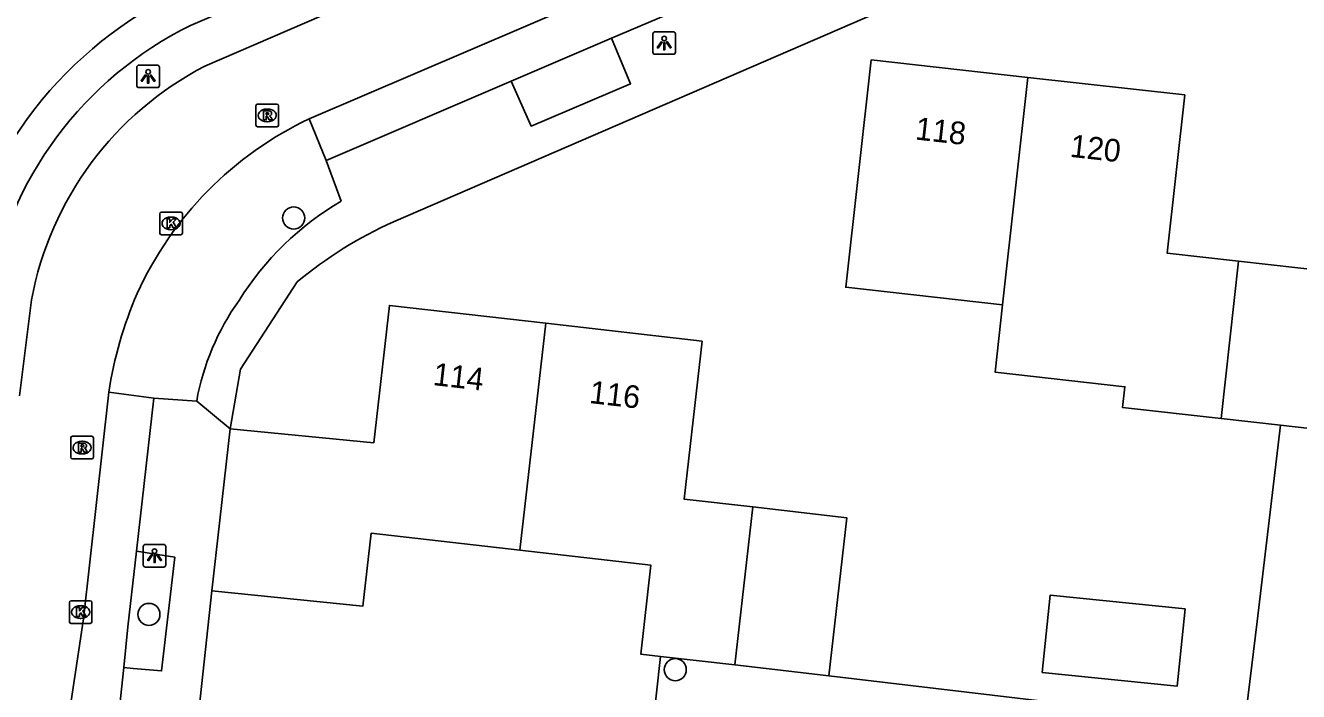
# Model space of a CAD drawing. Extents: x 162026 to 163499, y 387297 to 388169.
# Drawn here: x 162195.3 to 162251.6, y 387941.9 to 387971.3 of the extents above; entities that cross this region are included whole.
import ezdxf

# ---------------------------------------------------------------- set-up
doc = ezdxf.new("R2010")
doc.units = 0
for name, color, linetype in [('IMGEO_Boom', 7, 'Continuous'), ('IMGEO_Kolk', 7, 'Continuous'), ('IMGEO_Lichtpunt', 7, 'Continuous'), ('IMGEO_Pand', 7, 'Continuous'), ('IMGEO_Pand_nummerreeks', 7, 'Continuous'), ('IMGEO_Parkeervlak_open', 7, 'Continuous'), ('IMGEO_Rijbaan_lokaal_open', 7, 'Continuous'), ('IMGEO_Rioolput', 7, 'Continuous'), ('IMGEO_Voetpad_open', 7, 'Continuous')]:
    doc.layers.add(name, color=color, linetype=linetype)

msp = doc.modelspace()

# ---------------------------------------------------------------- linework, layer by layer
at = {"layer": 'IMGEO_Boom'}
for centre in [(162207.145, 387962.827), (162200.744, 387945.31), (162224.012, 387942.869)]:
    msp.add_circle(centre, 0.489, dxfattribs=at)
at = {"layer": 'IMGEO_Kolk'}
for p, q in [((162201.224, 387962.163), (162201.224, 387963.015)), ((162201.299, 387963.089), (162202.151, 387963.089)), ((162201.712, 387962.869), (162201.737, 387962.869)), ((162202.225, 387963.015), (162202.225, 387962.163)), ((162201.735, 387962.309), (162201.71, 387962.309)), ((162202.151, 387962.089), (162201.299, 387962.089)), ((162197.227, 387944.987), (162197.227, 387945.839)), ((162197.302, 387945.913), (162198.154, 387945.913)), ((162197.715, 387945.693), (162197.74, 387945.693)), ((162198.228, 387945.839), (162198.228, 387944.987)), ((162198.154, 387944.913), (162197.302, 387944.913)), ((162197.738, 387945.133), (162197.713, 387945.133))]:
    msp.add_line(p, q, dxfattribs=at)
for points in [[(162201.224, 387962.163), (162201.224, 387963.015)], [(162201.299, 387963.089), (162202.151, 387963.089)], [(162202.225, 387963.015), (162202.225, 387962.163)], [(162201.545, 387962.789), (162201.668, 387962.789), (162201.668, 387962.638), (162201.798, 387962.789), (162201.962, 387962.789), (162201.816, 387962.638), (162201.969, 387962.389), (162201.817, 387962.389), (162201.732, 387962.553), (162201.668, 387962.486), (162201.668, 387962.389), (162201.545, 387962.389), (162201.545, 387962.789)], [(162202.151, 387962.089), (162201.299, 387962.089)], [(162197.227, 387944.987), (162197.227, 387945.839)], [(162197.302, 387945.913), (162198.154, 387945.913)], [(162197.548, 387945.613), (162197.671, 387945.613), (162197.671, 387945.462), (162197.801, 387945.613), (162197.965, 387945.613), (162197.819, 387945.462), (162197.972, 387945.213), (162197.82, 387945.213), (162197.735, 387945.377), (162197.671, 387945.31), (162197.671, 387945.213), (162197.548, 387945.213), (162197.548, 387945.613)], [(162198.228, 387945.839), (162198.228, 387944.987)], [(162198.154, 387944.913), (162197.302, 387944.913)]]:
    msp.add_lwpolyline(points, dxfattribs=at)
for centre, start, end in [((162201.301, 387963.013), 91.552, 178.448), ((162201.301, 387963.013), 91.552, 178.448), ((162202.149, 387963.013), 1.552, 88.448), ((162202.149, 387963.013), 1.552, 88.448), ((162201.301, 387962.165), 181.552, 268.448), ((162201.301, 387962.165), 181.552, 268.448), ((162202.149, 387962.165), 271.552, 358.448), ((162202.149, 387962.165), 271.552, 358.448), ((162197.304, 387945.837), 91.552, 178.448), ((162197.304, 387945.837), 91.552, 178.448), ((162198.152, 387945.837), 1.552, 88.448), ((162198.152, 387945.837), 1.552, 88.448), ((162197.304, 387944.989), 181.552, 268.448), ((162197.304, 387944.989), 181.552, 268.448), ((162198.152, 387944.989), 271.552, 358.448), ((162198.152, 387944.989), 271.552, 358.448)]:
    msp.add_arc(centre, 0.0765, start, end, dxfattribs=at)
for centre, major_axis, ratio, start_param, end_param in [((162201.711, 387962.589), (-0.387, 0.002), 0.722429, 4.712389, 7.853982), ((162201.736, 387962.589), (-0.39, 0.002), 0.717154, 1.570796, 4.712389), ((162197.714, 387945.413), (-0.387, 0.002), 0.722429, 4.712389, 7.853982), ((162197.739, 387945.413), (-0.39, 0.002), 0.717154, 1.570796, 4.712389)]:
    msp.add_ellipse(centre, major_axis=major_axis, ratio=ratio, start_param=start_param, end_param=end_param, dxfattribs=at)
at = {"layer": 'IMGEO_Lichtpunt'}
for p, q in [((162223.027, 387970.961), (162223.027, 387970.154)), ((162223.027, 387970.961), (162223.027, 387970.154)), ((162223.929, 387971.056), (162223.121, 387971.056)), ((162223.929, 387971.056), (162223.121, 387971.056)), ((162224.023, 387970.154), (162224.023, 387970.961)), ((162224.023, 387970.154), (162224.023, 387970.961)), ((162201.113, 387969.584), (162200.305, 387969.584)), ((162201.113, 387969.584), (162200.305, 387969.584)), ((162223.121, 387970.06), (162223.929, 387970.06)), ((162223.121, 387970.06), (162223.929, 387970.06)), ((162200.211, 387969.489), (162200.211, 387968.682)), ((162200.211, 387969.489), (162200.211, 387968.682)), ((162201.207, 387968.682), (162201.207, 387969.489)), ((162201.207, 387968.682), (162201.207, 387969.489)), ((162200.305, 387968.588), (162201.113, 387968.588)), ((162200.305, 387968.588), (162201.113, 387968.588)), ((162200.496, 387948.306), (162200.496, 387947.499)), ((162200.496, 387948.306), (162200.496, 387947.499)), ((162201.398, 387948.401), (162200.59, 387948.401)), ((162201.398, 387948.401), (162200.59, 387948.401)), ((162201.492, 387947.499), (162201.492, 387948.306)), ((162201.492, 387947.499), (162201.492, 387948.306)), ((162200.59, 387947.405), (162201.398, 387947.405)), ((162200.59, 387947.405), (162201.398, 387947.405))]:
    msp.add_line(p, q, dxfattribs=at)
for points in [[(162223.401, 387970.625), (162223.44, 387970.597), (162223.252, 387970.335), (162223.214, 387970.362), (162223.401, 387970.625)], [(162223.503, 387970.577), (162223.55, 387970.577), (162223.55, 387970.255), (162223.503, 387970.255), (162223.503, 387970.577)], [(162223.613, 387970.597), (162223.651, 387970.624), (162223.838, 387970.362), (162223.799, 387970.334), (162223.613, 387970.597)], [(162200.585, 387969.153), (162200.624, 387969.125), (162200.436, 387968.863), (162200.398, 387968.89), (162200.585, 387969.153)], [(162200.687, 387969.105), (162200.734, 387969.105), (162200.734, 387968.783), (162200.687, 387968.783), (162200.687, 387969.105)], [(162200.797, 387969.125), (162200.835, 387969.152), (162201.022, 387968.89), (162200.983, 387968.862), (162200.797, 387969.125)], [(162200.87, 387947.97), (162200.909, 387947.942), (162200.721, 387947.68), (162200.683, 387947.707), (162200.87, 387947.97)], [(162200.972, 387947.922), (162201.019, 387947.922), (162201.019, 387947.6), (162200.972, 387947.6), (162200.972, 387947.922)], [(162201.082, 387947.942), (162201.12, 387947.969), (162201.307, 387947.707), (162201.268, 387947.679), (162201.082, 387947.942)]]:
    msp.add_lwpolyline(points, dxfattribs=at)
for centre in [(162223.526, 387970.759), (162200.71, 387969.287), (162200.995, 387948.104)]:
    msp.add_circle(centre, 0.0994, dxfattribs=at)
for centre, start, end in [((162223.121, 387970.961), 90, 180), ((162223.121, 387970.961), 90, 180), ((162223.929, 387970.961), 0, 90), ((162223.929, 387970.961), 0, 90), ((162223.121, 387970.154), 180, 270), ((162223.121, 387970.154), 180, 270), ((162223.929, 387970.154), 270, 0), ((162223.929, 387970.154), 270, 360), ((162200.305, 387969.489), 90, 180), ((162200.305, 387969.489), 90, 180), ((162201.113, 387969.489), 0, 90), ((162201.113, 387969.489), 0, 90), ((162200.305, 387968.682), 180, 270), ((162200.305, 387968.682), 180, 270), ((162201.113, 387968.682), 270, 0), ((162201.113, 387968.682), 270, 360), ((162200.59, 387948.306), 90, 180), ((162200.59, 387948.306), 90, 180), ((162201.398, 387948.306), 0, 90), ((162201.398, 387948.306), 0, 90), ((162200.59, 387947.499), 180, 270), ((162200.59, 387947.499), 180, 270), ((162201.398, 387947.499), 270, 0), ((162201.398, 387947.499), 270, 360)]:
    msp.add_arc(centre, 0.0946, start, end, dxfattribs=at)
at = {"layer": 'IMGEO_Pand'}
for points in [[(162238.482, 387958.996), (162231.553, 387959.77), (162232.675, 387969.813), (162239.605, 387969.039)], [(162239.605, 387969.039), (162238.482, 387958.996)], [(162239.605, 387969.039), (162246.536, 387968.264), (162245.755, 387961.273), (162248.918, 387960.92)], [(162248.141, 387953.962), (162248.918, 387960.92)], [(162248.918, 387960.92), (162252.845, 387960.481), (162252.599, 387958.276)], [(162218.29, 387958.173), (162211.378, 387958.966), (162210.682, 387952.898), (162204.331, 387953.511)], [(162248.141, 387953.962), (162243.787, 387954.448), (162243.891, 387955.373), (162238.149, 387956.015), (162238.482, 387958.996)], [(162217.14, 387948.148), (162218.29, 387958.173)], [(162218.29, 387958.173), (162225.201, 387957.38), (162224.401, 387950.407), (162227.44, 387950.058)], [(162252.599, 387958.276), (162252.068, 387953.523), (162250.767, 387953.668)], [(162250.767, 387953.668), (162248.141, 387953.962)], [(162204.331, 387953.511), (162203.528, 387946.354)], [(162226.642, 387943.08), (162227.44, 387950.058)], [(162227.44, 387950.058), (162231.597, 387949.581), (162230.797, 387942.603)], [(162203.528, 387946.354), (162210.202, 387945.675), (162210.57, 387948.902), (162217.14, 387948.148)], [(162223.356, 387943.457), (162222.489, 387943.556), (162222.939, 387947.482), (162217.14, 387948.148)], [(162246.552, 387945.55), (162246.201, 387942.133), (162240.238, 387942.745), (162240.588, 387946.163), (162246.552, 387945.55)], [(162226.642, 387943.08), (162223.356, 387943.457)], [(162230.797, 387942.603), (162226.642, 387943.08)]]:
    msp.add_lwpolyline(points, dxfattribs=at)
at = {"layer": 'IMGEO_Parkeervlak_open'}
for points in [[(162216.765, 387968.87), (162221.195, 387970.769)], [(162207.831, 387967.208), (162208.58, 387965.361)], [(162200.956, 387954.871), (162198.971, 387955.129)], [(162199.636, 387942.961), (162199.817, 387944.765), (162200.197, 387948.098)]]:
    msp.add_lwpolyline(points, dxfattribs=at)
at = {"layer": 'IMGEO_Rijbaan_lokaal_open'}
for points in [[(162216.634, 387975.343), (162203.22, 387969.54)], [(162207.831, 387967.208), (162224.442, 387974.33)], [(162195.555, 387959.213), (162195.019, 387954.965)], [(162196.666, 387937.17), (162197.855, 387945.12), (162198.971, 387955.129)], [(162230.797, 387942.603), (162245.241, 387940.89), (162249.184, 387940.423), (162249.731, 387944.997), (162250.767, 387953.668)], [(162215.708, 387935.479), (162222.811, 387938.496), (162223.356, 387943.457)]]:
    msp.add_lwpolyline(points, dxfattribs=at)
for centre, radius, start, end in [((162209.987, 387956.509), 14.683, 117.4437, 169.3885), ((162214.592, 387952.936), 15.792, 115.3485, 155.4888), ((162216.631, 387952.416), 17.867, 156.6835, 171.266)]:
    msp.add_arc(centre, radius, start, end, dxfattribs=at)
at = {"layer": 'IMGEO_Rioolput'}
for p, q in [((162205.474, 387966.933), (162205.474, 387967.785)), ((162205.549, 387967.859), (162206.401, 387967.859)), ((162205.962, 387967.639), (162205.987, 387967.639)), ((162206.475, 387967.785), (162206.475, 387966.933)), ((162206.401, 387966.859), (162205.549, 387966.859)), ((162205.985, 387967.079), (162205.96, 387967.079)), ((162197.29, 387952.254), (162197.29, 387953.106)), ((162197.365, 387953.18), (162198.217, 387953.18)), ((162197.778, 387952.96), (162197.803, 387952.96)), ((162198.291, 387953.106), (162198.291, 387952.254)), ((162198.217, 387952.18), (162197.365, 387952.18)), ((162197.801, 387952.4), (162197.776, 387952.4))]:
    msp.add_line(p, q, dxfattribs=at)
for points in [[(162205.474, 387966.933), (162205.474, 387967.785)], [(162205.549, 387967.859), (162206.401, 387967.859)], [(162206.063, 387967.557), (162205.811, 387967.559), (162205.811, 387967.159)], [(162205.811, 387967.159), (162205.935, 387967.159), (162205.935, 387967.321), (162205.946, 387967.321)], [(162205.989, 387967.478), (162205.935, 387967.478), (162205.935, 387967.397)], [(162205.935, 387967.397), (162205.987, 387967.397)], [(162206.475, 387967.785), (162206.475, 387966.933)], [(162206.401, 387966.859), (162205.549, 387966.859)], [(162205.993, 387967.292), (162206.064, 387967.159), (162206.204, 387967.159), (162206.139, 387967.285)], [(162197.29, 387952.254), (162197.29, 387953.106)], [(162197.365, 387953.18), (162198.217, 387953.18)], [(162197.879, 387952.878), (162197.627, 387952.88), (162197.627, 387952.48)], [(162197.805, 387952.799), (162197.751, 387952.799), (162197.751, 387952.718)], [(162197.751, 387952.718), (162197.803, 387952.718)], [(162198.291, 387953.106), (162198.291, 387952.254)], [(162198.217, 387952.18), (162197.365, 387952.18)], [(162197.627, 387952.48), (162197.751, 387952.48), (162197.751, 387952.642), (162197.762, 387952.642)], [(162197.809, 387952.613), (162197.88, 387952.48), (162198.02, 387952.48), (162197.955, 387952.606)]]:
    msp.add_lwpolyline(points, dxfattribs=at)
for centre, radius, start, end in [((162205.551, 387967.783), 0.0765, 91.552, 178.448), ((162205.551, 387967.783), 0.0765, 91.552, 178.448), ((162205.945, 387967.268), 0.0533, 26.0293, 88.6989), ((162205.971, 387967.586), 0.19, 274.7715, 282.9687), ((162205.995, 387967.382), 0.0964, 77.0061, 93.1865), ((162206.009, 387967.439), 0.0378, 276.6634, 79.6772), ((162206.062, 387967.447), 0.109, 350.3612, 89.416), ((162206.06, 387967.447), 0.112, 277.5842, 350.9817), ((162206.044, 387967.232), 0.108, 29.5134, 73.7905), ((162206.399, 387967.783), 0.0765, 1.552, 88.448), ((162206.399, 387967.783), 0.0765, 1.552, 88.448), ((162205.551, 387966.935), 0.0765, 181.552, 268.448), ((162205.551, 387966.935), 0.0765, 181.552, 268.448), ((162206.399, 387966.935), 0.0765, 271.552, 358.448), ((162206.399, 387966.935), 0.0765, 271.552, 358.448), ((162197.367, 387953.104), 0.0765, 91.552, 178.448), ((162197.367, 387953.104), 0.0765, 91.552, 178.448), ((162197.787, 387952.907), 0.19, 274.7715, 282.9687), ((162197.811, 387952.703), 0.0964, 77.0061, 93.1865), ((162197.825, 387952.76), 0.0378, 276.6634, 79.6772), ((162197.878, 387952.768), 0.109, 350.3612, 89.416), ((162197.876, 387952.768), 0.112, 277.5842, 350.9817), ((162198.215, 387953.104), 0.0765, 1.552, 88.448), ((162198.215, 387953.104), 0.0765, 1.552, 88.448), ((162197.367, 387952.256), 0.0765, 181.552, 268.448), ((162197.367, 387952.256), 0.0765, 181.552, 268.448), ((162197.761, 387952.589), 0.0533, 26.0293, 88.6989), ((162197.86, 387952.553), 0.108, 29.5134, 73.7905), ((162198.215, 387952.256), 0.0765, 271.552, 358.448), ((162198.215, 387952.256), 0.0765, 271.552, 358.448)]:
    msp.add_arc(centre, radius, start, end, dxfattribs=at)
for centre, major_axis, ratio, start_param, end_param in [((162205.961, 387967.359), (-0.387, 0.002), 0.722429, 4.712389, 7.853982), ((162205.986, 387967.359), (-0.39, 0.002), 0.717154, 1.570796, 4.712389), ((162197.777, 387952.68), (-0.387, 0.002), 0.722429, 4.712389, 7.853982), ((162197.802, 387952.68), (-0.39, 0.002), 0.717154, 1.570796, 4.712389)]:
    msp.add_ellipse(centre, major_axis=major_axis, ratio=ratio, start_param=start_param, end_param=end_param, dxfattribs=at)
at = {"layer": 'IMGEO_Voetpad_open'}
for points in [[(162254.101, 387981.349), (162240.014, 387974.97), (162211.554, 387962.659)], [(162202.587, 387971.334), (162215.884, 387977.057), (162216.634, 387975.343)], [(162225.236, 387972.502), (162221.195, 387970.769)], [(162221.195, 387970.769), (162222.039, 387968.759), (162217.641, 387966.886), (162216.765, 387968.87)], [(162216.765, 387968.87), (162208.58, 387965.361)], [(162208.58, 387965.361), (162209.247, 387963.572)], [(162207.296, 387959.999), (162204.796, 387956.145), (162204.331, 387953.511)], [(162200.956, 387954.871), (162200.197, 387948.098)], [(162202.856, 387954.738), (162200.956, 387954.871)], [(162202.856, 387954.738), (162204.331, 387953.511)], [(162200.197, 387948.098), (162201.885, 387947.845), (162201.303, 387942.811), (162200.052, 387942.924), (162199.636, 387942.961)], [(162203.528, 387946.354), (162202.28, 387934.764), (162202.317, 387934.183), (162203.737, 387930.179)], [(162199.636, 387942.961), (162198.981, 387936.929)]]:
    msp.add_lwpolyline(points, dxfattribs=at)
for centre, radius, start, end in [((162209.874, 387956.607), 17.965, 116.7271, 170.792), ((162209.805, 387956.652), 16.361, 116.181, 170.6106), ((162215.924, 387952.171), 13.212, 120.3539, 147.9351), ((162219.291, 387945.535), 18.791, 114.316, 129.6706), ((162213.702, 387952.792), 11.019, 144.5368, 169.827)]:
    msp.add_arc(centre, radius, start, end, dxfattribs=at)

# ---------------------------------------------------------------- texts
at = {"layer": 'IMGEO_Pand_nummerreeks'}
for s, rotation, p in [('118', 353.6235, (162234.59, 387966.299)), ('120', 353.6235, (162241.431, 387965.534)), ('114', 353.4568, (162213.272, 387955.447)), ('116', 353.4547, (162220.185, 387954.654))]:
    msp.add_text(s, height=1, rotation=rotation, dxfattribs=at).set_placement(p)

doc.saveas('drawing.dxf')
